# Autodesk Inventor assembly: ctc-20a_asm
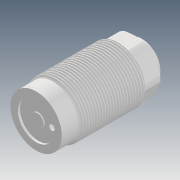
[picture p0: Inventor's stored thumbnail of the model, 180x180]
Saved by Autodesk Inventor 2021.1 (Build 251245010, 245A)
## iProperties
Created: 2018-08
Part Number: ctc-20a_asm
Description: STEP AP203
Document SubType Name: Assembly
Designer: user
Title: ctc-20a_asm.STEP
Revision Number: ÈÎºÎ
Sending System: SolidWorks 2015
Preprocessor: SwSTEP 2.0
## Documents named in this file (6)
- D:\Vault_2016\Projekty\Clamptek\Hydraulic\CTC\Inventor\ctc-20a\ctc-20a_asm.iam
- D:\Vault_2016\Projekty\Clamptek\Hydraulic\CTC\Inventor\ctc-20a\CTC-20BT.ipt
- D:\Vault_2016\Projekty\Clamptek\Hydraulic\CTC\Inventor\ctc-20a\CTC-20AHSG.ipt
- D:\Vault_2016\Projekty\Clamptek\Hydraulic\CTC\Inventor\ctc-20a\CTC-20HG.ipt
- D:\Vault_2016\Projekty\Clamptek\Hydraulic\CTC\Inventor\ctc-20a\CTC-20MD.ipt
- D:\Vault_2016\Projekty\Clamptek\Hydraulic\CTC\Inventor\ctc-20a\CTC-20DP.ipt
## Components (5 placed, 5 different names)
1. CTC-20BT_1
2. CTC-20AHSG_2
3. CTC-20HG_3
4. CTC-20MD_4
5. CTC-20DP_5
